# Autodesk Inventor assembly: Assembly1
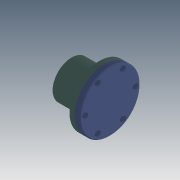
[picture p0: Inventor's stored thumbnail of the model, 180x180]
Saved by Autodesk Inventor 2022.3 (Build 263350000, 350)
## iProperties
Created: 2023-08
Part Number: Assembly1
Document SubType Name: Assembly
Designer: irinventor.com
Author: irinventor.com
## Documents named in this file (5)
- D:\INVENTOR Doc\Inventor CLASSES\Khoshnami@ Shiraz\Breakout assembly\Assembly1.iam
- D:\INVENTOR Doc\Inventor CLASSES\Khoshnami@ Shiraz\Breakout assembly\Basic Part.ipt
- D:\INVENTOR Doc\Inventor CLASSES\Khoshnami@ Shiraz\Breakout assembly\Cap.ipt
- D:\INVENTOR Doc\Inventor CLASSES\Khoshnami@ Shiraz\Breakout assembly\Copper Gasket.ipt
- D:\INVENTOR Doc\Inventor CLASSES\Khoshnami@ Shiraz\Breakout assembly\cylinder Insert.ipt
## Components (4 placed, 4 different names)
1. cylinder Insert:1 — Mate:1, Mate:2, Flush:1
2. Basic Part:1 — Mate:1, Mate:2, Flush:1, Mate:3, Mate:4, Mate:5, Mate:6, Mate:7
3. Cap:1 — Mate:3, Mate:4, Mate:5
4. Copper Gasket:1 — Mate:6, Mate:7
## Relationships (8: Mate 7, Flush 1)
- Mate:1: cylinder Insert:1 ↔ Basic Part:1
- Mate:2: cylinder Insert:1 ↔ Basic Part:1
- Flush:1: cylinder Insert:1 ↔ Basic Part:1
- Mate:3: Basic Part:1 ↔ Cap:1
- Mate:4: Basic Part:1 ↔ Cap:1
- Mate:5: Basic Part:1 ↔ Cap:1
- Mate:6: Basic Part:1 ↔ Copper Gasket:1
- Mate:7: Basic Part:1 ↔ Copper Gasket:1
